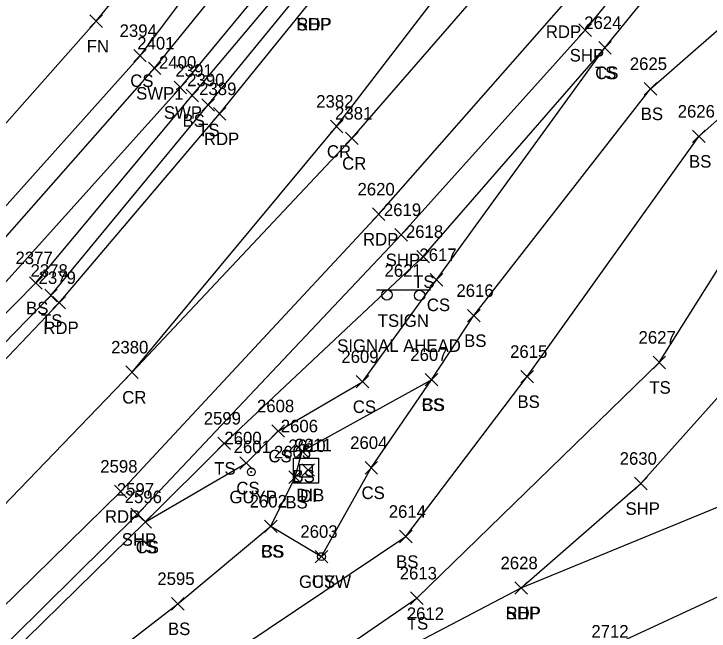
# Model space of a CAD drawing. Extents: x 1477930 to 1480780, y 774090 to 784647.
# Drawn here: x 1479285.9 to 1479397, y 774680.3 to 774778.8 of the extents above; entities that cross this region are included whole.
import ezdxf

# ---------------------------------------------------------------- set-up
doc = ezdxf.new("R2010")
doc.units = 0
for name, color, linetype in [('D_A', 7, 'Continuous'), ('D_I', 7, 'Continuous'), ('D_TIC', 7, 'Continuous'), ('DS', 7, 'Continuous'), ('L_A', 7, 'Continuous'), ('L_I', 7, 'Continuous'), ('L_TIC', 7, 'Continuous'), ('LELB', 7, 'Continuous'), ('LFNC', 7, 'Continuous'), ('P_A', 7, 'Continuous'), ('P_I', 7, 'Continuous'), ('P_TIC', 7, 'Continuous'), ('PET', 7, 'Continuous'), ('PRC', 7, 'Continuous'), ('PSP', 7, 'Continuous'), ('R_A', 7, 'Continuous'), ('R_I', 7, 'Continuous'), ('R_TIC', 7, 'Continuous'), ('RSW', 7, 'Continuous'), ('S_A', 7, 'Continuous'), ('S_C', 7, 'Continuous'), ('S_I', 7, 'Continuous'), ('SSGN', 7, 'Continuous'), ('U_A', 7, 'Continuous'), ('U_I', 7, 'Continuous'), ('UPGW', 7, 'Continuous')]:
    doc.layers.add(name, color=color, linetype=linetype)

msp = doc.modelspace()

# ---------------------------------------------------------------- linework, layer by layer
at = {"layer": 'D_TIC'}
for points in [[(1479331.96, 774705.02), (1479333.96, 774707.02)], [(1479333.96, 774705.02), (1479331.96, 774707.02)]]:
    msp.add_lwpolyline(points, dxfattribs=at)
at = {"layer": 'DS'}
for p, q in [((1479330.6, 774707.89), (1479334.6, 774707.89)), ((1479330.6, 774703.89), (1479330.6, 774707.89)), ((1479334.6, 774707.89), (1479334.6, 774703.89)), ((1479331.6, 774704.89), (1479331.6, 774706.89)), ((1479331.6, 774706.89), (1479333.6, 774706.89)), ((1479332.61, 774705.89), (1479332.61, 774705.89)), ((1479332.61, 774705.89), (1479332.61, 774705.89)), ((1479333.6, 774706.89), (1479333.6, 774704.89)), ((1479333.6, 774704.89), (1479331.6, 774704.89)), ((1479334.6, 774703.89), (1479330.6, 774703.89))]:
    msp.add_line(p, q, dxfattribs=at)
at = {"layer": 'L_TIC'}
for points in [[(1479298.07, 774776.69), (1479300.07, 774778.69)], [(1479300.07, 774776.69), (1479298.07, 774778.69)], [(1479379.37, 774772.44), (1479381.37, 774774.44)], [(1479381.37, 774772.44), (1479379.37, 774774.44)], [(1479379.37, 774772.44), (1479381.37, 774774.44)], [(1479381.37, 774772.44), (1479379.37, 774774.44)], [(1479305.08, 774771.18), (1479307.08, 774773.18)], [(1479307.08, 774771.18), (1479305.08, 774773.18)], [(1479386.65, 774765.89), (1479388.65, 774767.89)], [(1479388.65, 774765.89), (1479386.65, 774767.89)], [(1479313.43, 774764.82), (1479315.43, 774766.82)], [(1479315.43, 774764.82), (1479313.43, 774766.82)], [(1479315.96, 774763.31), (1479317.96, 774765.31)], [(1479317.96, 774763.31), (1479315.96, 774765.31)], [(1479394.36, 774758.3), (1479396.36, 774760.3)], [(1479396.36, 774758.3), (1479394.36, 774760.3)], [(1479350.31, 774739.09), (1479352.31, 774741.09)], [(1479352.31, 774739.09), (1479350.31, 774741.09)], [(1479288.44, 774734.89), (1479290.44, 774736.89)], [(1479290.44, 774734.89), (1479288.44, 774736.89)], [(1479352.46, 774735.39), (1479354.46, 774737.39)], [(1479354.46, 774735.39), (1479352.46, 774737.39)], [(1479290.85, 774732.88), (1479292.85, 774734.88)], [(1479292.85, 774732.88), (1479290.85, 774734.88)], [(1479358.43, 774729.67), (1479360.43, 774731.67)], [(1479360.43, 774729.67), (1479358.43, 774731.67)], [(1479388.05, 774722.2), (1479390.05, 774724.2)], [(1479390.05, 774722.2), (1479388.05, 774724.2)], [(1479351.65, 774719.44), (1479353.65, 774721.44)], [(1479353.65, 774719.44), (1479351.65, 774721.44)], [(1479351.65, 774719.44), (1479353.65, 774721.44)], [(1479353.65, 774719.44), (1479351.65, 774721.44)], [(1479366.95, 774719.93), (1479368.95, 774721.93)], [(1479368.95, 774719.93), (1479366.95, 774721.93)], [(1479340.64, 774719.12), (1479342.64, 774721.12)], [(1479342.64, 774719.12), (1479340.64, 774721.12)], [(1479327.15, 774711.24), (1479329.15, 774713.24)], [(1479329.15, 774711.24), (1479327.15, 774713.24)], [(1479318.53, 774709.27), (1479320.53, 774711.27)], [(1479320.53, 774709.27), (1479318.53, 774711.27)], [(1479331.01, 774708.04), (1479333.01, 774710.04)], [(1479333.01, 774708.04), (1479331.01, 774710.04)], [(1479322.03, 774706.13), (1479324.03, 774708.13)], [(1479324.03, 774706.13), (1479322.03, 774708.13)], [(1479342.04, 774705.38), (1479344.04, 774707.38)], [(1479344.04, 774705.38), (1479342.04, 774707.38)], [(1479329.87, 774703.88), (1479331.87, 774705.88)], [(1479331.87, 774703.88), (1479329.87, 774705.88)], [(1479305.94, 774696.73), (1479307.94, 774698.73)], [(1479307.94, 774696.73), (1479305.94, 774698.73)], [(1479305.94, 774696.73), (1479307.94, 774698.73)], [(1479307.94, 774696.73), (1479305.94, 774698.73)], [(1479325.98, 774696.03), (1479327.98, 774698.03)], [(1479327.98, 774696.03), (1479325.98, 774698.03)], [(1479325.98, 774696.03), (1479327.98, 774698.03)], [(1479327.98, 774696.03), (1479325.98, 774698.03)], [(1479347.56, 774694.39), (1479349.56, 774696.39)], [(1479349.56, 774694.39), (1479347.56, 774696.39)], [(1479334.08, 774691.19), (1479336.08, 774693.19)], [(1479336.08, 774691.19), (1479334.08, 774693.19)], [(1479349.31, 774684.54), (1479351.31, 774686.54)], [(1479351.31, 774684.54), (1479349.31, 774686.54)], [(1479311.11, 774683.66), (1479313.11, 774685.66)], [(1479313.11, 774683.66), (1479311.11, 774685.66)]]:
    msp.add_lwpolyline(points, dxfattribs=at)
at = {"layer": 'LELB'}
for points in [[(1478962.33, 774641.76), (1478963.97, 774605.71), (1478989.2, 774585.18), (1479035.48, 774565.64), (1479062.1, 774571.6), (1479071.52, 774575.06), (1479101.02, 774601.1), (1479154.98, 774641.54), (1479197.13, 774670.38), (1479247.47, 774711.89), (1479280.68, 774743.82), (1479306.08, 774772.18), (1479339.44, 774816.42), (1479355.38, 774843.56), (1479373.73, 774868.57)], [(1478740.27, 774421.37), (1478804.49, 774448.68), (1478839.51, 774461.41), (1478900.12, 774482.9), (1478933.76, 774495.55), (1478952.86, 774503.55), (1479014.49, 774533.68), (1479069.06, 774560.68), (1479112.01, 774585.56), (1479167.75, 774622.17), (1479210.47, 774656.8), (1479257.79, 774698.97), (1479291.85, 774733.88), (1479316.96, 774764.31), (1479351.88, 774806.96), (1479375.4, 774842.78), (1479390.8, 774862.22)], [(1479239.1, 774628.15), (1479242.92, 774638.24), (1479276.86, 774668.3), (1479306.94, 774697.73), (1479319.53, 774710.27), (1479351.31, 774740.09), (1479380.37, 774773.44), (1479412.56, 774813.05), (1479431.34, 774845.03)], [(1479014.49, 774533.68), (1479043.28, 774555.25), (1479065.32, 774566.41), (1479074.11, 774570.76), (1479108.86, 774587.86), (1479163.89, 774628.29), (1479207.81, 774659.29), (1479255.33, 774701.37), (1479289.44, 774735.89), (1479314.43, 774765.82), (1479350.18, 774808.35), (1479373.39, 774844.03)], [(1479239.1, 774628.15), (1479244.5, 774634.75), (1479251.92, 774639.74), (1479281.73, 774661.2), (1479312.11, 774684.66), (1479326.98, 774697.03), (1479330.87, 774704.88), (1479332.01, 774709.04), (1479352.65, 774720.44), (1479359.43, 774730.67), (1479387.65, 774766.89), (1479404.19, 774781.43), (1479420.83, 774800.43), (1479431.1, 774813.94), (1479434.19, 774831.92), (1479437.58, 774844.49)], [(1479244.5, 774634.75), (1479252.74, 774637.23), (1479275, 774646.05), (1479317.84, 774674.82), (1479348.56, 774695.39), (1479367.95, 774720.93), (1479395.36, 774759.3), (1479410.62, 774772.85), (1479423.92, 774796.13), (1479428.44, 774804.28), (1479431.1, 774813.94)], [(1479244.5, 774634.75), (1479253.67, 774635.16), (1479275, 774646.05), (1479321.56, 774665.78), (1479350.31, 774685.54), (1479389.05, 774723.2), (1479417.5, 774768.3), (1479423.92, 774796.13)], [(1479306.94, 774697.73), (1479323.03, 774707.13), (1479328.15, 774712.24), (1479341.64, 774720.12), (1479353.46, 774736.39), (1479380.37, 774773.44)], [(1479326.98, 774697.03), (1479335.08, 774692.19), (1479343.04, 774706.38), (1479352.65, 774720.44)]]:
    msp.add_lwpolyline(points, dxfattribs=at)
at = {"layer": 'LFNC'}
msp.add_lwpolyline([(1478963.8, 774657.83), (1478978.61, 774653.25), (1478971.45, 774628.81), (1478963.97, 774605.71), (1479000.4, 774593.85), (1479046.12, 774579.13), (1479053.93, 774576.72), (1479097.31, 774607.25), (1479152.18, 774645.44), (1479192.1, 774673.94), (1479241.74, 774716.53), (1479274.15, 774749.58), (1479299.07, 774777.69), (1479333.92, 774820.28), (1479359.32, 774855.82), (1479370.21, 774870.3)], dxfattribs=at)
at = {"layer": 'P_TIC'}
for points in [[(1479376.2, 774775.25), (1479378.2, 774777.25)], [(1479378.2, 774775.25), (1479376.2, 774777.25)], [(1479317.8, 774761.89), (1479319.8, 774763.89)], [(1479319.8, 774761.89), (1479317.8, 774763.89)], [(1479336.5, 774759.88), (1479338.5, 774761.88)], [(1479338.5, 774759.88), (1479336.5, 774761.88)], [(1479338.94, 774757.98), (1479340.94, 774759.98)], [(1479340.94, 774757.98), (1479338.94, 774759.98)], [(1479343.22, 774745.86), (1479345.22, 774747.86)], [(1479345.22, 774745.86), (1479343.22, 774747.86)], [(1479346.8, 774742.57), (1479348.8, 774744.57)], [(1479348.8, 774742.57), (1479346.8, 774744.57)], [(1479292.15, 774731.73), (1479294.15, 774733.73)], [(1479294.15, 774731.73), (1479292.15, 774733.73)], [(1479303.81, 774720.63), (1479305.81, 774722.63)], [(1479305.81, 774720.63), (1479303.81, 774722.63)], [(1479303.81, 774720.63), (1479305.81, 774722.63)], [(1479305.81, 774720.63), (1479303.81, 774722.63)], [(1479385.11, 774702.86), (1479387.11, 774704.86)], [(1479387.11, 774702.86), (1479385.11, 774704.86)], [(1479301.99, 774701.6), (1479303.99, 774703.6)], [(1479303.99, 774701.6), (1479301.99, 774703.6)], [(1479304.63, 774697.93), (1479306.63, 774699.93)], [(1479306.63, 774697.93), (1479304.63, 774699.93)], [(1479365.99, 774686.18), (1479367.99, 774688.18)], [(1479367.99, 774686.18), (1479365.99, 774688.18)], [(1479365.99, 774686.18), (1479367.99, 774688.18)], [(1479367.99, 774686.18), (1479365.99, 774688.18)]]:
    msp.add_lwpolyline(points, dxfattribs=at)
at = {"layer": 'PET'}
for points in [[(1479231.31, 774636.06), (1479272.54, 774672.78), (1479302.99, 774702.6), (1479344.22, 774746.86), (1479373.44, 774780.01), (1479405.23, 774818.27), (1479428.23, 774848.68), (1479447.93, 774875.75), (1479460.71, 774894.51), (1479479.69, 774925.18), (1479480.31, 774927.38), (1479493.45, 774951.2), (1479514.74, 775006.53), (1479531.7, 775055.13), (1479548.14, 775106.72), (1479553.83, 775125.43), (1479564.45, 775161.29), (1479573.74, 775193.3), (1479576.58, 775204.25), (1479585.43, 775238.68), (1479593.96, 775273.34), (1479599.4, 775295.6)], [(1479168.73, 774620.31), (1479212.4, 774655.38), (1479259.7, 774697.56), (1479293.15, 774732.73), (1479318.8, 774762.89), (1479333.57, 774781.21), (1479355.81, 774805.14), (1479380.51, 774839), (1479394.88, 774859.45), (1479419.72, 774898.43), (1479440.51, 774934.48), (1479462.36, 774978.06), (1479482.36, 775026.15), (1479497.52, 775065.91), (1479509.28, 775100.79), (1479510.93, 775118.31)], [(1479234.45, 774632.83), (1479239.1, 774628.15), (1479289.14, 774648.12), (1479321.9, 774663.73), (1479351.45, 774679.08), (1479366.99, 774687.18), (1479407.96, 774704.03), (1479416.46, 774738.94), (1479422.81, 774766.95), (1479432.79, 774813.6), (1479435.56, 774829.5), (1479438.63, 774843.63), (1479441.63, 774858.96), (1479447.93, 774875.75)]]:
    msp.add_lwpolyline(points, dxfattribs=at)
at = {"layer": 'PRC'}
for points in [[(1480015.89, 775005.87), (1479971.79, 774982.46), (1479929.14, 774959.03), (1479892.61, 774942.34), (1479860.44, 774925.31), (1479806.49, 774896.54), (1479658.45, 774815.54), (1479643.75, 774807.57), (1479597.62, 774782.97), (1479555.61, 774761.16), (1479513.42, 774740.32), (1479471, 774718.6), (1479432.73, 774701.1), (1479418.32, 774694.97), (1479344.83, 774660.92), (1479298.6, 774640.39), (1479262.12, 774624.4), (1479219.63, 774609.01), (1479186.74, 774593.83)], [(1479194.24, 774620.68), (1479224.8, 774645.46), (1479270.23, 774685.77), (1479304.81, 774721.63), (1479337.5, 774760.88), (1479368.49, 774801.2), (1479398.58, 774843.3), (1479429.86, 774889.66)], [(1479304.81, 774721.63), (1479339.94, 774758.98), (1479373.28, 774797.31), (1479405.3, 774837.12), (1479437.9, 774882.86)]]:
    msp.add_lwpolyline(points, dxfattribs=at)
at = {"layer": 'PSP'}
for points in [[(1479234.45, 774632.83), (1479231.31, 774636.06), (1479275.79, 774669.49), (1479305.63, 774698.93), (1479347.8, 774743.57), (1479377.2, 774776.25), (1479409.48, 774815.47), (1479431.34, 774845.03), (1479437.58, 774844.49), (1479438.63, 774843.63)], [(1479366.99, 774687.18), (1479386.11, 774703.86), (1479401.89, 774721.48), (1479416.46, 774738.94)]]:
    msp.add_lwpolyline(points, dxfattribs=at)
at = {"layer": 'R_TIC'}
for points in [[(1479307.42, 774769.17), (1479309.42, 774771.17)], [(1479309.42, 774769.17), (1479307.42, 774771.17)], [(1479311.53, 774766.11), (1479313.53, 774768.11)], [(1479313.53, 774766.11), (1479311.53, 774768.11)]]:
    msp.add_lwpolyline(points, dxfattribs=at)
at = {"layer": 'RSW'}
for points in [[(1479274.17, 774731.39), (1479308.42, 774770.17), (1479343.53, 774813.46), (1479368.77, 774847.04), (1479380.89, 774863.8), (1479383.37, 774867.44), (1479386.24, 774871.51), (1479407.11, 774905.13), (1479428.53, 774941.71), (1479450.08, 774982.66), (1479469.96, 775030.3), (1479484.01, 775070.5), (1479497.13, 775105.7)], [(1479277.58, 774728.25), (1479312.53, 774767.11), (1479348.01, 774809.99), (1479373.39, 774844.03), (1479387.54, 774864.22), (1479390.19, 774868.27), (1479411.38, 774902.61), (1479432.83, 774938.99), (1479454.5, 774980.05), (1479474.41, 775028.7), (1479489.03, 775068.75), (1479501.66, 775103.93)]]:
    msp.add_lwpolyline(points, dxfattribs=at)
at = {"layer": 'SSGN'}
for p, q in [((1479343.87, 774734.8), (1479352.47, 774734.8)), ((1479347.89, 774733.9), (1479347.89, 774733.9))]:
    msp.add_line(p, q, dxfattribs=at)
for centre in [(1479345.53, 774733.97), (1479350.75, 774733.9)]:
    msp.add_circle(centre, 0.833, dxfattribs=at)
at = {"layer": 'UPGW'}
for centre, radius in [((1479323.86, 774705.71), 0.625), ((1479323.86, 774705.71), 0.0833), ((1479335.08, 774692.19), 0.625), ((1479335.08, 774692.19), 0.0833)]:
    msp.add_circle(centre, radius, dxfattribs=at)

# ---------------------------------------------------------------- texts
at = {"layer": 'D_A'}
for s, p in [('DIB', (1479331.06, 774701.02)), ('DI', (1479331.66, 774700.89))]:
    msp.add_text(s, height=2, dxfattribs=at).set_placement(p)
at = {"layer": 'D_I'}
for s, p in [('2610', (1479329.78, 774708.89)), ('2611', (1479330.78, 774709.02))]:
    msp.add_text(s, height=2, dxfattribs=at).set_placement(p)
at = {"layer": 'L_A'}
for s, p in [('FN', (1479297.55, 774772.69)), ('TS', (1479378.77, 774768.44)), ('CS', (1479378.81, 774768.44)), ('CS', (1479304.52, 774767.18)), ('BS', (1479386.09, 774761.89)), ('BS', (1479312.87, 774760.82)), ('TS', (1479315.37, 774759.31)), ('BS', (1479393.8, 774754.3)), ('TS', (1479349.72, 774735.09)), ('BS', (1479287.88, 774730.89)), ('CS', (1479351.91, 774731.39)), ('TS', (1479290.26, 774728.88)), ('BS', (1479357.87, 774725.67)), ('TS', (1479387.46, 774718.2)), ('CS', (1479340.08, 774715.12)), ('CS', (1479351.09, 774715.44)), ('BS', (1479351.09, 774715.44)), ('BS', (1479366.39, 774715.93)), ('CS', (1479326.59, 774707.24)), ('TS', (1479317.94, 774705.27)), ('BS', (1479330.45, 774704.04)), ('CS', (1479321.47, 774702.13)), ('CS', (1479341.48, 774701.38)), ('BS', (1479329.31, 774699.88)), ('TS', (1479305.35, 774692.73)), ('CS', (1479305.39, 774692.73)), ('CS', (1479325.42, 774692.03)), ('BS', (1479325.42, 774692.03)), ('BS', (1479347, 774690.39)), ('CS', (1479333.53, 774687.19)), ('TS', (1479348.72, 774680.54)), ('BS', (1479310.55, 774679.66))]:
    msp.add_text(s, height=2, dxfattribs=at).set_placement(p)
at = {"layer": 'L_I'}
for s, p in [('2624', (1479377.06, 774776.44)), ('2624', (1479377.06, 774776.44)), ('2394', (1479302.82, 774775.18)), ('2625', (1479384.34, 774769.89)), ('2391', (1479311.74, 774768.82)), ('2390', (1479313.62, 774767.31)), ('2626', (1479391.99, 774762.3)), ('2618', (1479348.57, 774743.09)), ('2617', (1479350.72, 774739.39)), ('2377', (1479286.18, 774738.89)), ('2378', (1479288.59, 774736.88)), ('2616', (1479356.63, 774733.67)), ('2627', (1479385.74, 774726.2)), ('2615', (1479365.21, 774723.93)), ('2609', (1479338.25, 774723.12)), ('2607', (1479349.27, 774723.44)), ('2607', (1479349.27, 774723.44)), ('2608', (1479324.77, 774715.24)), ('2599', (1479316.26, 774713.27)), ('2606', (1479328.57, 774712.04)), ('2600', (1479319.56, 774710.13)), ('2604', (1479339.66, 774709.38)), ('2605', (1479327.48, 774707.88)), ('2596', (1479303.63, 774700.73)), ('2596', (1479303.63, 774700.73)), ('2602', (1479323.6, 774700.03)), ('2602', (1479323.6, 774700.03)), ('2614', (1479345.82, 774698.39)), ('2603', (1479331.7, 774695.19)), ('2613', (1479347.57, 774688.54)), ('2595', (1479308.85, 774687.66))]:
    msp.add_text(s, height=2, dxfattribs=at).set_placement(p)
at = {"layer": 'P_A'}
for s, p in [('SHP', (1479331.1, 774776.21)), ('RDP', (1479331.06, 774776.21)), ('RDP', (1479370.92, 774775.01)), ('SHP', (1479374.74, 774771.25)), ('RDP', (1479316.29, 774757.89)), ('CR', (1479335.94, 774755.88)), ('CR', (1479338.38, 774753.98)), ('RDP', (1479341.71, 774741.86)), ('SHP', (1479345.33, 774738.57)), ('RDP', (1479290.64, 774727.73)), ('CR', (1479303.24, 774716.63)), ('CR', (1479303.24, 774716.63)), ('SHP', (1479383.65, 774698.86)), ('RDP', (1479300.47, 774697.6)), ('SHP', (1479303.16, 774693.93)), ('SHP', (1479364.52, 774682.18)), ('RDP', (1479364.48, 774682.18))]:
    msp.add_text(s, height=2, dxfattribs=at).set_placement(p)
at = {"layer": 'P_I'}
for s, p in [('2389', (1479315.53, 774765.89)), ('2382', (1479334.24, 774763.88)), ('2381', (1479337.25, 774761.98)), ('2620', (1479340.83, 774749.86)), ('2619', (1479345.05, 774746.57)), ('2379', (1479289.88, 774735.73)), ('2380', (1479301.46, 774724.63)), ('2380', (1479301.46, 774724.63)), ('2630', (1479382.72, 774706.86)), ('2598', (1479299.73, 774705.6)), ('2597', (1479302.37, 774701.93)), ('2628', (1479363.68, 774690.18)), ('2628', (1479363.68, 774690.18)), ('2612', (1479348.71, 774682.08))]:
    msp.add_text(s, height=2, dxfattribs=at).set_placement(p)
at = {"layer": 'R_A'}
for s, p in [('SWP1', (1479305.46, 774765.17)), ('SWP', (1479309.89, 774762.11))]:
    msp.add_text(s, height=2, dxfattribs=at).set_placement(p)
at = {"layer": 'R_I'}
for s, p in [('2401', (1479305.64, 774773.17)), ('2400', (1479309.11, 774770.11))]:
    msp.add_text(s, height=2, dxfattribs=at).set_placement(p)
at = {"layer": 'S_A'}
msp.add_text('TSIGN', height=2, dxfattribs=at).set_placement((1479344.07, 774728.88))
at = {"layer": 'S_C'}
msp.add_text('SIGNAL AHEAD', height=2, dxfattribs=at).set_placement((1479337.58, 774724.88))
at = {"layer": 'S_I'}
msp.add_text('2621', height=2, dxfattribs=at).set_placement((1479345.15, 774736.88))
at = {"layer": 'U_A'}
for s, p in [('GUYP', (1479320.37, 774700.71)), ('GUYW', (1479331.48, 774687.19))]:
    msp.add_text(s, height=2, dxfattribs=at).set_placement(p)
at = {"layer": 'U_I'}
for s, p in [('2601', (1479321.04, 774708.71)), ('2603', (1479331.7, 774695.19)), ('2712', (1479378.2, 774679.26))]:
    msp.add_text(s, height=2, dxfattribs=at).set_placement(p)

doc.saveas('drawing.dxf')
